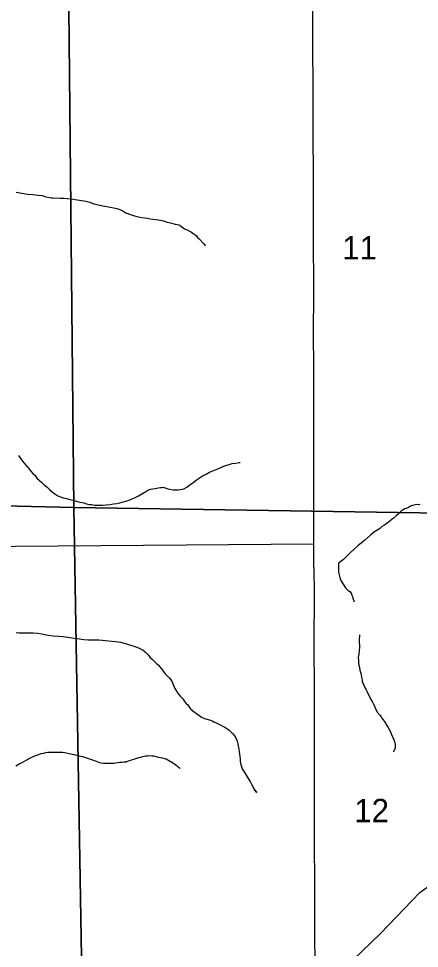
# Model space of a CAD drawing. Extents: x 2010165 to 2382125, y 1060529 to 1407316.
# Drawn here: x 2175609 to 2179406, y 1212363 to 1221171 of the extents above; entities that cross this region are included whole.
import ezdxf

# ---------------------------------------------------------------- set-up
doc = ezdxf.new("R2010")
doc.units = 0
for name, color, linetype in [('GM_X_City_Street', 7, 'Continuous'), ('GM_X_Minor_River', 7, 'Continuous'), ('GM_X_Section', 7, 'Continuous'), ('GM_X_Section_Text', 7, 'Continuous'), ('GM_X_State_Route', 7, 'Continuous')]:
    doc.layers.add(name, color=color, linetype=linetype)

msp = doc.modelspace()

# ---------------------------------------------------------------- linework, layer by layer
at = {"layer": 'GM_X_City_Street'}
for points in [[(2178423, 1211913.8), (2179036.1, 1212505.8), (2179410.9, 1212892), (2180199.4, 1213453.7), (2180714.7, 1213808.7), (2181543, 1214385.7), (2181756.8, 1214469.5), (2182287.3, 1214668.4), (2183161.5, 1214990.5), (2183684.1, 1215177.3), (2184009.7, 1215310), (2184380.9, 1215465.7), (2184751.3, 1215661.5), (2186628.9, 1216659.1), (2186954.8, 1216831.2), (2187007.7, 1216859)], [(2172347.5, 1216149.6), (2178406.5, 1216195.6)]]:
    msp.add_lwpolyline(points, dxfattribs=at)
at = {"layer": 'GM_X_Minor_River'}
for points in [[(2175585.2, 1219527.6), (2175637.7, 1219517), (2175692, 1219508.4), (2175742.3, 1219503.7), (2175792.6, 1219499), (2175832.8, 1219494), (2175867.2, 1219482.8), (2175901.4, 1219477.7), (2175919.6, 1219474.2), (2175937.6, 1219472.6), (2176001.9, 1219470.3), (2176036, 1219469.2), (2176072.2, 1219466.2), (2176108.3, 1219463.1), (2176144.6, 1219458), (2176186.9, 1219451.1), (2176245.3, 1219440.6), (2176283.7, 1219431.6), (2176322.2, 1219416.5), (2176364.6, 1219405.6), (2176406.9, 1219396.6), (2176443.2, 1219389.6), (2176477.5, 1219384.4), (2176511.7, 1219379.3), (2176540, 1219372), (2176568.3, 1219362.7), (2176596.7, 1219351.4), (2176625.2, 1219332.1), (2176669.8, 1219315.2), (2176706.3, 1219302.1), (2176744.6, 1219293.1), (2176776.8, 1219287.9), (2176805.1, 1219282.6), (2176829.2, 1219279.2), (2176855.4, 1219273.9), (2176881.6, 1219270.6), (2176905.7, 1219267.2), (2176929.9, 1219263.8), (2176954, 1219260.4), (2176978.3, 1219255.1), (2176996.5, 1219249.5), (2177014.7, 1219244), (2177032.8, 1219240.4), (2177049, 1219234.8), (2177069.2, 1219229.3), (2177091.4, 1219223.9), (2177109.5, 1219220.3), (2177125.7, 1219216.8), (2177139.9, 1219211.1), (2177156.2, 1219199.5), (2177178.8, 1219180), (2177211.3, 1219166.8), (2177233.6, 1219155.3), (2177245.9, 1219147.6), (2177258.1, 1219139.9), (2177272.4, 1219130.3), (2177282.6, 1219122.5), (2177292.9, 1219112.7), (2177303.3, 1219098.9), (2177317.7, 1219085.3), (2177359.1, 1219040.2), (2177369.4, 1219026.4), (2177377.6, 1219020.6)], [(2177377.6, 1219020.6), (2177369.4, 1219026.4)], [(2175608.4, 1217032.4), (2175621, 1217012.7), (2175639.7, 1216989.1), (2175658.4, 1216963.4), (2175679.2, 1216937.9), (2175701.9, 1216912.4), (2175722.7, 1216886.8), (2175743.3, 1216863.3), (2175764, 1216841.7), (2175782.7, 1216818.1), (2175807.3, 1216796.7), (2175829.9, 1216777.2), (2175848.5, 1216757.6), (2175879.2, 1216732.3), (2175901.9, 1216710.8), (2175926.5, 1216689.4), (2175953.2, 1216668), (2175979.7, 1216650.6), (2176004, 1216641.2), (2176032.3, 1216631.9), (2176062.6, 1216624.7), (2176092.9, 1216615.4), (2176123.2, 1216608.2), (2176155.5, 1216599), (2176187.9, 1216589.8), (2176226.2, 1216582.8), (2176252.4, 1216575.5), (2176276.7, 1216568.1), (2176302.8, 1216566.8), (2176329, 1216563.4), (2176363.1, 1216562.3), (2176401.2, 1216561.3), (2176439.2, 1216566.3), (2176475.2, 1216569.3), (2176509.1, 1216574.2), (2176539.1, 1216579), (2176569, 1216583.8), (2176590.9, 1216590.4), (2176612.8, 1216597), (2176634.7, 1216603.6), (2176656.6, 1216610.2), (2176684.4, 1216621), (2176714.1, 1216633.8), (2176743.7, 1216650.6), (2176814.8, 1216690.6), (2176832.5, 1216703.2), (2176858.4, 1216711.9), (2176880.3, 1216716.5), (2176904.2, 1216721.1), (2176930.2, 1216725.8), (2176952.1, 1216730.4), (2176968.1, 1216730.8), (2176980.2, 1216731.1), (2176994.3, 1216727.5), (2177006.5, 1216721.8)], [(2177006.5, 1216721.8), (2177022.7, 1216716.2), (2177040.8, 1216712.7), (2177069, 1216707.4), (2177093.1, 1216706), (2177119.2, 1216706.7), (2177141.2, 1216709.3), (2177163.2, 1216711.9), (2177181.1, 1216718.4), (2177202.7, 1216733), (2177230.2, 1216753.8), (2177261.7, 1216776.7), (2177291.2, 1216797.6), (2177320.7, 1216818.4), (2177350.2, 1216839.3), (2177385.9, 1216856.3), (2177415.5, 1216873.1), (2177449.2, 1216888.1), (2177479, 1216898.9), (2177510.7, 1216911.8), (2177542.4, 1216926.6), (2177572.2, 1216937.5), (2177602, 1216948.3), (2177631.9, 1216955.1), (2177665.8, 1216960), (2177693.8, 1216964.8), (2177707.8, 1216967.1)], [(2179409, 1216568.1), (2179399, 1216565.9), (2179386.9, 1216567.6), (2179369, 1216565.1), (2179353, 1216562.7), (2179339.1, 1216558.3), (2179321.2, 1216551.8), (2179301.4, 1216541.2), (2179279.7, 1216530.6), (2179265.7, 1216526.2), (2179251.9, 1216517.8), (2179234.2, 1216505.3), (2179212.7, 1216486.7), (2179189.2, 1216464), (2179159.8, 1216439.1), (2179128.4, 1216412.2), (2179097, 1216389.3), (2179069.4, 1216370.5)], [(2179069.4, 1216370.5), (2179045.7, 1216355.8), (2179026.1, 1216339.2), (2178970.9, 1216303.6), (2178945.5, 1216280.9), (2178918.1, 1216256.1), (2178888.7, 1216231.2), (2178857.3, 1216206.3), (2178821.9, 1216177.2), (2178786.7, 1216146.2), (2178749.5, 1216111.1), (2178718.3, 1216080.1), (2178685.1, 1216047.1), (2178663.5, 1216030.5), (2178649.8, 1216018.1), (2178639.9, 1216013.8), (2178638.6, 1215985.7), (2178639.4, 1215955.6), (2178640.2, 1215927.5), (2178644.9, 1215901.5), (2178651.6, 1215877.6), (2178662.4, 1215847.8), (2178683.4, 1215812.2), (2178706.4, 1215778.6), (2178731.1, 1215753.2), (2178747.4, 1215743.6), (2178759.9, 1215727.8), (2178766.4, 1215709.9), (2178770.7, 1215698), (2178775.2, 1215680.1), (2178779.5, 1215670.1), (2178786, 1215650.2), (2178788.3, 1215645.9)], [(2175585.5, 1215355.2), (2175609.6, 1215353.8), (2175641.7, 1215352.7), (2175677.8, 1215353.6), (2175713.9, 1215352.6), (2175748, 1215351.5), (2175786.2, 1215348.4), (2175828.5, 1215343.5), (2175870.9, 1215332.6), (2175937.3, 1215324.3), (2175987.5, 1215321.6), (2176031.7, 1215316.8), (2176074, 1215311.8), (2176114.3, 1215304.9), (2176152.5, 1215299.8), (2176188.7, 1215294.8), (2176227, 1215287.8), (2176267.2, 1215286.8), (2176301.3, 1215285.7), (2176329.3, 1215286.4), (2176369.4, 1215287.5), (2176459.9, 1215277.8), (2176494.1, 1215274.7), (2176526.3, 1215271.5), (2176552.4, 1215268.2), (2176576.6, 1215264.8), (2176596.8, 1215259.3), (2176621.1, 1215249.9), (2176649.4, 1215242.6), (2176679.7, 1215231.4), (2176718.1, 1215220.4), (2176744.5, 1215209), (2176764.8, 1215199.5), (2176779, 1215193.8), (2176789.2, 1215188.1), (2176799.5, 1215178.3), (2176811.8, 1215168.6), (2176822.1, 1215156.8), (2176836.5, 1215143.2), (2176853.1, 1215123.5), (2176875.8, 1215100), (2176898.5, 1215076.5), (2176917, 1215058.9), (2176933.4, 1215045.3), (2176947.9, 1215029.6), (2176962.4, 1215011.9), (2176979, 1214990.3), (2176997.8, 1214964.7), (2177018.4, 1214943.1), (2177037, 1214923.6), (2177051.5, 1214905.9), (2177062, 1214888.1), (2177068.5, 1214868.2), (2177079.1, 1214848.4), (2177089.8, 1214824.6), (2177104.5, 1214798.8), (2177121.2, 1214773.2), (2177141.9, 1214749.6), (2177160.5, 1214730), (2177170.8, 1214718.3), (2177181.3, 1214702.5), (2177195.9, 1214682.8), (2177210.3, 1214669.1)], [(2178838.7, 1215332.4), (2178836.2, 1215276.1), (2178837.8, 1215219.9), (2178834.8, 1215181.7), (2178831.6, 1215149.5), (2178826.3, 1215123.2), (2178827.2, 1215089.1), (2178829.7, 1215071.1), (2178830, 1215061.1), (2178832.4, 1215047.1), (2178834.7, 1215037.1), (2178837.1, 1215021.1), (2178841.7, 1214999.1), (2178848.3, 1214979.2), (2178852.9, 1214957.3), (2178857.6, 1214931.3), (2178859.9, 1214921.3), (2178862.2, 1214907.3), (2178864.7, 1214889.3), (2178869.1, 1214877.4), (2178875.6, 1214859.5), (2178884, 1214843.6), (2178892.4, 1214829.8), (2178900.8, 1214814), (2178909.5, 1214792.1), (2178922.2, 1214766.3), (2178934.8, 1214744.6), (2178945.5, 1214720.8), (2178960.2, 1214695.1), (2178974.9, 1214669.3), (2178987.7, 1214641.6), (2179004.9, 1214599.9), (2179029.7, 1214572.4), (2179042.1, 1214556.7), (2179050.5, 1214544.8), (2179061, 1214527), (2179073.3, 1214515.3), (2179079.6, 1214505.4), (2179085.9, 1214495.6), (2179096.5, 1214475.8), (2179111, 1214456.1), (2179123.7, 1214434.3), (2179134.5, 1214404.5), (2179155.9, 1214352.9), (2179164.3, 1214341), (2179170.8, 1214321.1), (2179173.1, 1214311.1), (2179175.5, 1214297.1), (2179176, 1214277.1), (2179176.4, 1214263), (2179165, 1214238.6), (2179156.3, 1214224.7)], [(2177210.3, 1214669.1), (2177220.7, 1214655.3), (2177237.3, 1214633.7), (2177255.8, 1214616.1), (2177274.3, 1214600.5), (2177292.7, 1214586.9), (2177315.2, 1214571.5), (2177341.7, 1214554.1), (2177368.2, 1214540.7), (2177426.7, 1214524.2), (2177440.9, 1214518.6), (2177457.2, 1214508.9), (2177481.6, 1214499.6), (2177499.8, 1214492), (2177518.1, 1214482.4), (2177538.5, 1214470.9), (2177556.8, 1214461.4), (2177573.1, 1214451.8), (2177589.4, 1214440.1), (2177603.7, 1214430.5), (2177620.2, 1214414.9), (2177638.7, 1214397.3), (2177653.3, 1214377.6), (2177670, 1214351.9), (2177678.7, 1214326), (2177685.4, 1214302.1), (2177690.1, 1214278.1), (2177694.8, 1214250.2), (2177699.5, 1214224.2), (2177702.1, 1214202.2), (2177704.7, 1214180.1), (2177707.3, 1214158.1), (2177708.1, 1214132.1), (2177714.8, 1214104.1), (2177725.9, 1214064.3), (2177746.7, 1214036.7), (2177763.7, 1214003), (2177782.6, 1213971.4), (2177801.4, 1213943.8), (2177816, 1213920.1), (2177826.7, 1213898.3), (2177835.1, 1213882.4), (2177843.6, 1213866.6), (2177866.3, 1213839.1), (2177843.6, 1213866.6), (2177866.3, 1213839.1)], [(2175583.5, 1214094.2), (2175613.1, 1214111.1), (2175640.8, 1214123.9), (2175664.5, 1214136.5), (2175686.2, 1214149.1), (2175706, 1214161.7), (2175721.8, 1214168.2), (2175741.6, 1214178.7), (2175761.4, 1214187.3), (2175781.3, 1214193.8), (2175799.2, 1214200.3), (2175821, 1214208.9), (2175846.9, 1214213.6), (2175866.9, 1214218.1), (2175886.8, 1214222.7), (2175951, 1214222.4), (2175975, 1214223), (2175999.1, 1214223.6), (2176023.2, 1214222.3), (2176045.3, 1214218.8), (2176073.5, 1214213.6), (2176115.9, 1214204.6), (2176148.2, 1214195.4), (2176182.5, 1214188.3), (2176214.8, 1214181.1), (2176243.1, 1214171.8), (2176271.4, 1214162.5), (2176297.8, 1214151.2), (2176324.1, 1214143.8), (2176344.3, 1214136.3), (2176360.5, 1214130.8), (2176374.7, 1214125.1), (2176390.8, 1214121.5), (2176413, 1214118.1), (2176433.1, 1214116.6), (2176459.1, 1214117.3), (2176487.2, 1214118), (2176509.2, 1214118.6), (2176529.2, 1214121.1), (2176549.2, 1214123.7), (2176567.2, 1214126.1), (2176585.2, 1214126.6), (2176605.2, 1214129.1)], [(2176605.2, 1214129.1), (2176627.2, 1214131.7), (2176651, 1214140.4), (2176670.9, 1214146.9), (2176688.8, 1214151.4), (2176708.7, 1214158), (2176728.6, 1214164.5), (2176746.5, 1214171), (2176762.4, 1214175.4), (2176774.4, 1214177.8), (2176786.3, 1214182.1), (2176798.2, 1214184.4), (2176812.2, 1214186.8), (2176832.2, 1214187.3), (2176856.2, 1214190), (2176874.3, 1214188.4), (2176890.4, 1214186.8), (2176910.6, 1214181.3), (2176930.8, 1214175.9), (2176951, 1214172.4), (2176971.1, 1214168.9), (2176987.3, 1214163.3), (2177005.5, 1214157.8), (2177046.2, 1214134.7), (2177060.5, 1214127.1), (2177074.7, 1214119.4), (2177087, 1214111.7), (2177099.2, 1214102), (2177113.6, 1214090.3), (2177123.9, 1214080.6), (2177134.1, 1214072.8), (2177140.3, 1214068.9)]]:
    msp.add_lwpolyline(points, dxfattribs=at)
at = {"layer": 'GM_X_Section'}
for points in [[(2175291.6, 1221576.6), (2176081.6, 1221585.6), (2176133.3, 1216538.6), (2170517.3, 1216673.9), (2170463.9, 1221481), (2171925.4, 1221504.9), (2174244.4, 1221580)], [(2178737.9, 1221615.8), (2181485, 1221648.7), (2181662, 1216455.1), (2176133.3, 1216538.6), (2176081.6, 1221585.6)], [(2176133.3, 1216538.6), (2176227.8, 1210985.9), (2170583.9, 1211012.5), (2170517.3, 1216673.9)], [(2181662, 1216455.1), (2181835.9, 1210948.1), (2176227.8, 1210985.9), (2176133.3, 1216538.6)]]:
    msp.add_lwpolyline(points, close=True, dxfattribs=at)
at = {"layer": 'GM_X_State_Route'}
for points in [[(2178414, 1212494.4), (2178414, 1212898.9), (2178411, 1213442.6), (2178411, 1213779.3), (2178411.8, 1214118.2), (2178412.5, 1214393.1), (2178411, 1214671.7), (2178408.7, 1215388.7), (2178410.2, 1215584.5), (2178411.8, 1215777.3), (2178406.5, 1216038.3), (2178406.5, 1216195.6), (2178406.5, 1216660.3), (2178405.7, 1217078.3), (2178405, 1217409.7), (2178405, 1217830.7), (2178403.5, 1218222.3), (2178404.2, 1218532.6), (2178401.2, 1219172.7), (2178401.2, 1219680.3), (2178398.2, 1220076.4), (2178399.7, 1220578), (2178397.4, 1220849.9), (2178396.7, 1221153.4), (2178397.4, 1221386.9)], [(2178694.4, 1208551.7), (2178678.7, 1208611.8), (2178619.6, 1208847.9), (2178581.9, 1208994.7), (2178557.8, 1209089.6), (2178547.3, 1209169.5), (2178538.3, 1209243.3), (2178527.7, 1209401.4), (2178520.2, 1209476), (2178507.4, 1209650.7), (2178480.3, 1209994.9), (2178453.2, 1210373.7), (2178441.1, 1210535.6), (2178436.6, 1210616.9), (2178429.1, 1210722.4), (2178423.8, 1210860.2), (2178417, 1210934.8), (2178420, 1211117), (2178418.5, 1211380.6), (2178418.5, 1211660), (2178423, 1211913.8), (2178418.5, 1212219.6), (2178414, 1212489.2), (2178414, 1212494.4)]]:
    msp.add_lwpolyline(points, dxfattribs=at)

# ---------------------------------------------------------------- texts
at = {"layer": 'GM_X_Section_Text'}
for s, p in [('11', (2178674, 1218889.5)), ('12', (2178788.4, 1213558.4))]:
    msp.add_text(s, height=221, rotation=0.00001, dxfattribs=at).set_placement(p)

doc.saveas('drawing.dxf')
